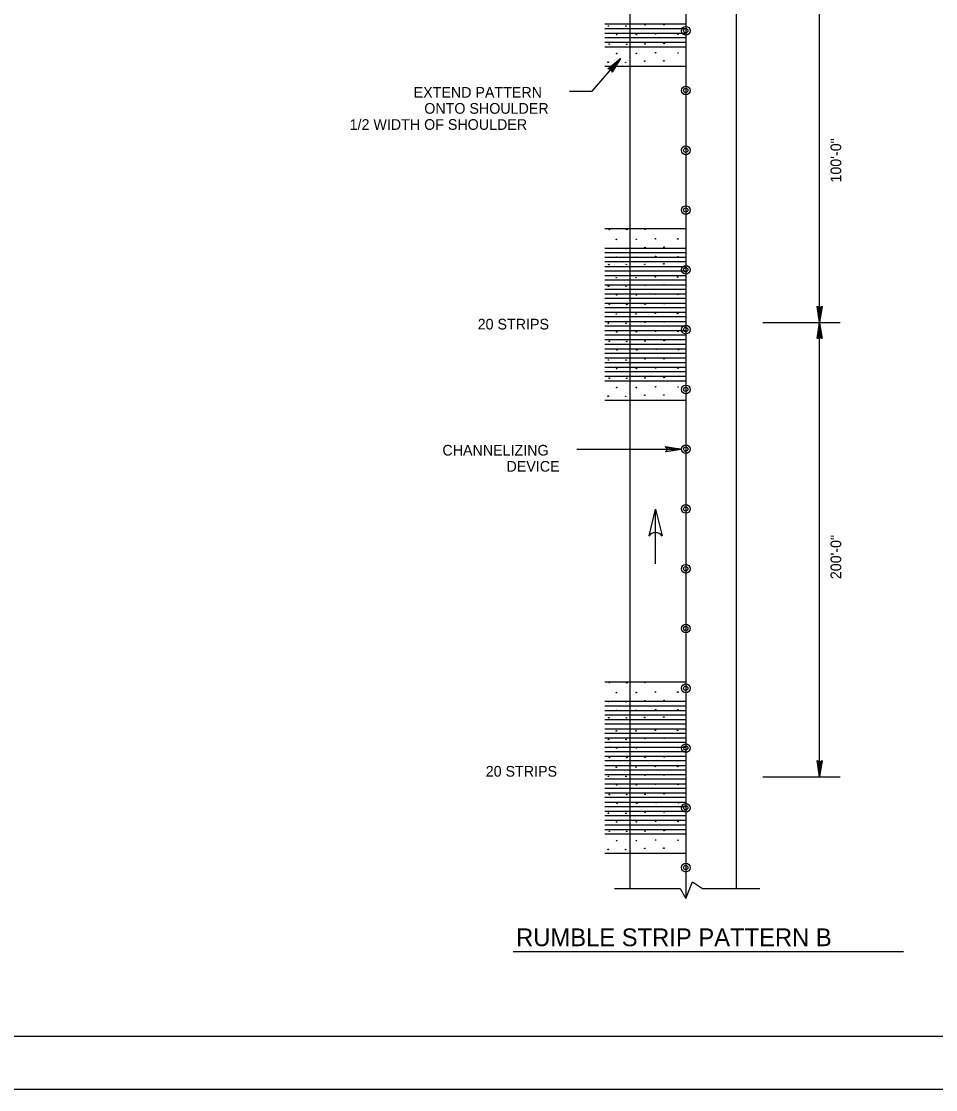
# Model space of a CAD drawing. Extents: x 632008 to 634206, y 294231 to 297795.
# Drawn here: x 632266.3 to 632523.5, y 294230.6 to 294531.2 of the extents above; entities that cross this region are included whole.
import ezdxf

# ---------------------------------------------------------------- set-up
doc = ezdxf.new("R2010")
doc.units = 0
for name, color, linetype in [('1', 7, 'Continuous'), ('Level 1', 7, 'Continuous'), ('Level 2', 7, 'Continuous'), ('Level 3', 7, 'Continuous'), ('PLT-BNDY', 7, 'Continuous')]:
    doc.layers.add(name, color=color, linetype=linetype)

msp = doc.modelspace()

# ---------------------------------------------------------------- linework, layer by layer
at = {"layer": '1'}
msp.add_line((632404.57, 294269.52), (632514.41, 294269.52), dxfattribs=at)
msp.add_lwpolyline([(632833.86, 294245.62), (632833.86, 294809.62), (632047.86, 294809.62), (632047.86, 294245.62), (632833.86, 294245.62), (632833.86, 294271.98), (632633.86, 294271.98), (632633.86, 294336.66), (632833.86, 294336.66), (632833.86, 294365.62), (632633.86, 294365.62), (632633.86, 294245.62), (632712.66, 294245.62), (632712.66, 294271.98), (632712.66, 294245.62), (632789.66, 294245.62), (632789.66, 294271.98), (632789.66, 294259.66), (632833.86, 294259.66)], dxfattribs=at)
at = {"layer": 'Level 1'}
msp.add_line((632422.57, 294410.77), (632451.94, 294410.77), dxfattribs=at)
at = {"layer": 'Level 2'}
for p, q in [((632437.46, 294798.64), (632437.46, 294287.23)), ((632453.13, 294798.64), (632453.17, 294284.41)), ((632467.47, 294287.23), (632467.47, 294798.64)), ((632490.81, 294446.46), (632490.81, 294540.43)), ((632430.37, 294530.44), (632453.13, 294530.44)), ((632430.37, 294529.19), (632453.13, 294529.19)), ((632430.37, 294527.86), (632453.13, 294527.86)), ((632430.37, 294526.62), (632453.13, 294526.62)), ((632430.37, 294525.28), (632453.13, 294525.28)), ((632430.37, 294524.04), (632453.13, 294524.04)), ((632426.81, 294511.49), (632434.77, 294520.76)), ((632430.37, 294518.58), (632453.13, 294518.58)), ((632420.49, 294511.49), (632426.81, 294511.49)), ((632430.37, 294472.85), (632453.13, 294472.85)), ((632430.37, 294467.39), (632453.13, 294467.39)), ((632430.37, 294466.15), (632453.13, 294466.15)), ((632430.37, 294464.81), (632453.13, 294464.81)), ((632430.37, 294463.57), (632453.13, 294463.57)), ((632430.37, 294462.23), (632453.13, 294462.23)), ((632430.37, 294460.99), (632453.13, 294460.99)), ((632430.37, 294459.66), (632453.13, 294459.66)), ((632430.37, 294458.42), (632453.13, 294458.42)), ((632430.37, 294457.08), (632453.13, 294457.08)), ((632430.37, 294455.84), (632453.13, 294455.84)), ((632430.37, 294454.5), (632453.13, 294454.5)), ((632430.37, 294453.26), (632453.13, 294453.26)), ((632430.37, 294451.93), (632453.13, 294451.93)), ((632430.37, 294450.69), (632453.13, 294450.69)), ((632430.37, 294449.35), (632453.13, 294449.35)), ((632430.37, 294448.11), (632453.13, 294448.11)), ((632430.37, 294446.77), (632453.13, 294446.77)), ((632430.37, 294445.53), (632453.13, 294445.53)), ((632430.37, 294444.2), (632453.13, 294444.2)), ((632474.86, 294446.46), (632496.63, 294446.46)), ((632490.81, 294318.66), (632490.81, 294446.46)), ((632430.37, 294442.95), (632453.13, 294442.95)), ((632430.37, 294441.62), (632453.13, 294441.62)), ((632430.37, 294440.38), (632453.13, 294440.38)), ((632430.37, 294439.04), (632453.13, 294439.04)), ((632430.37, 294437.8), (632453.13, 294437.8)), ((632430.37, 294436.47), (632453.13, 294436.47)), ((632430.37, 294435.22), (632453.13, 294435.22)), ((632430.37, 294433.89), (632453.13, 294433.89)), ((632430.37, 294432.65), (632453.13, 294432.65)), ((632430.37, 294431.31), (632453.13, 294431.31)), ((632430.37, 294430.07), (632453.13, 294430.07)), ((632430.37, 294424.61), (632453.13, 294424.61)), ((632442.89, 294386.4), (632444.65, 294393.96)), ((632444.65, 294393.96), (632446.57, 294386.4)), ((632444.65, 294378.51), (632444.65, 294393.96)), ((632430.37, 294345.35), (632453.13, 294345.35)), ((632430.37, 294339.89), (632453.13, 294339.89)), ((632430.37, 294338.64), (632453.13, 294338.64)), ((632430.37, 294337.31), (632453.13, 294337.31)), ((632430.37, 294336.07), (632453.13, 294336.07)), ((632430.37, 294334.73), (632453.13, 294334.73)), ((632430.37, 294333.49), (632453.13, 294333.49)), ((632430.37, 294332.15), (632453.13, 294332.15)), ((632430.37, 294330.91), (632453.13, 294330.91)), ((632430.37, 294329.58), (632453.13, 294329.58)), ((632430.37, 294328.34), (632453.13, 294328.34)), ((632430.37, 294327), (632453.13, 294327)), ((632430.37, 294325.76), (632453.13, 294325.76)), ((632430.37, 294324.42), (632453.13, 294324.42)), ((632430.37, 294323.18), (632453.13, 294323.18)), ((632430.37, 294321.85), (632453.13, 294321.85)), ((632430.37, 294320.61), (632453.13, 294320.61)), ((632430.37, 294319.27), (632453.13, 294319.27)), ((632430.37, 294318.03), (632453.13, 294318.03)), ((632474.84, 294318.66), (632496.61, 294318.66)), ((632430.37, 294316.69), (632453.13, 294316.69)), ((632430.37, 294315.45), (632453.13, 294315.45)), ((632430.37, 294314.12), (632453.13, 294314.12)), ((632430.37, 294312.88), (632453.13, 294312.88)), ((632430.37, 294311.54), (632453.13, 294311.54)), ((632430.37, 294310.3), (632453.13, 294310.3)), ((632430.37, 294308.96), (632453.13, 294308.96)), ((632430.37, 294307.72), (632453.13, 294307.72)), ((632430.37, 294306.39), (632453.13, 294306.39)), ((632430.37, 294305.15), (632453.13, 294305.15)), ((632430.37, 294303.81), (632453.13, 294303.81)), ((632430.37, 294302.57), (632453.13, 294302.57)), ((632430.37, 294297.11), (632453.13, 294297.11))]:
    msp.add_line(p, q, dxfattribs=at)
for centre, radius in [((632431.42, 294529.87), 0.0832), ((632436.34, 294529.84), 0.0832), ((632441.72, 294530.14), 0.0832), ((632447.07, 294530.21), 0.0832), ((632453.17, 294528.53), 1.23), ((632453.17, 294528.54), 0.601), ((632433.71, 294527.42), 0.0832), ((632439.27, 294527.44), 0.0832), ((632444.69, 294527.62), 0.0832), ((632450.98, 294527.55), 0.0832), ((632431.64, 294524.77), 0.0832), ((632436.56, 294524.74), 0.0832), ((632441.72, 294524.84), 0.0832), ((632444.69, 294522.33), 0.0832), ((632447.1, 294524.96), 0.0832), ((632450.98, 294522.26), 0.0832), ((632431.34, 294519.68), 0.0832), ((632433.71, 294522.13), 0.0832), ((632436.27, 294519.65), 0.0832), ((632439.28, 294522.14), 0.0832), ((632441.64, 294519.96), 0.0832), ((632447, 294520.03), 0.0832), ((632453.17, 294511.71), 1.23), ((632453.17, 294511.73), 0.601), ((632453.17, 294494.89), 1.23), ((632453.17, 294494.91), 0.601), ((632453.17, 294478.08), 1.23), ((632453.17, 294478.09), 0.601), ((632431.65, 294472.61), 0.0832), ((632431.65, 294472.61), 0.0832), ((632436.58, 294472.58), 0.0832), ((632436.58, 294472.58), 0.0832), ((632441.74, 294472.68), 0.0832), ((632441.74, 294472.68), 0.0832), ((632433.67, 294469.82), 0.0832), ((632439.23, 294469.84), 0.0832), ((632444.64, 294470.02), 0.0832), ((632450.94, 294469.95), 0.0832), ((632431.4, 294467.29), 0.0832), ((632436.33, 294467.26), 0.0832), ((632441.71, 294467.56), 0.0832), ((632447.06, 294467.63), 0.0832), ((632431.53, 294462.74), 0.0832), ((632433.7, 294464.84), 0.0832), ((632436.46, 294462.71), 0.0832), ((632439.26, 294464.86), 0.0832), ((632441.62, 294462.81), 0.0832), ((632444.67, 294465.05), 0.0832), ((632446.99, 294462.94), 0.0832), ((632450.97, 294464.97), 0.0832), ((632453.17, 294461.26), 1.23), ((632444.6, 294459.26), 0.0832), ((632450.89, 294459.19), 0.0832), ((632453.17, 294461.27), 0.601), ((632431.43, 294456.66), 0.0832), ((632433.62, 294459.06), 0.0832), ((632436.36, 294456.63), 0.0832), ((632439.18, 294459.07), 0.0832), ((632441.74, 294456.94), 0.0832), ((632447.09, 294457.01), 0.0832), ((632433.73, 294454.22), 0.0832), ((632439.29, 294454.23), 0.0832), ((632444.7, 294454.42), 0.0832), ((632451, 294454.35), 0.0832), ((632431.65, 294451.56), 0.0832), ((632436.58, 294451.53), 0.0832), ((632441.74, 294451.63), 0.0832), ((632447.11, 294451.76), 0.0832), ((632433.62, 294448.84), 0.0832), ((632439.18, 294448.86), 0.0832), ((632444.6, 294449.05), 0.0832), ((632450.89, 294448.98), 0.0832), ((632431.42, 294446.27), 0.0832), ((632436.34, 294446.24), 0.0832), ((632441.72, 294446.54), 0.0832), ((632447.07, 294446.61), 0.0832), ((632453.17, 294444.44), 1.23), ((632453.17, 294444.45), 0.601), ((632431.64, 294441.16), 0.0832), ((632433.71, 294443.82), 0.0832), ((632436.56, 294441.13), 0.0832), ((632439.27, 294443.84), 0.0832), ((632441.72, 294441.23), 0.0832), ((632444.69, 294444.02), 0.0832), ((632447.1, 294441.36), 0.0832), ((632450.98, 294443.95), 0.0832), ((632433.85, 294438.71), 0.0832), ((632439.41, 294438.72), 0.0832), ((632444.83, 294438.91), 0.0832), ((632451.12, 294438.84), 0.0832), ((632431.42, 294435.9), 0.0832), ((632436.34, 294435.87), 0.0832), ((632441.72, 294436.17), 0.0832), ((632447.07, 294436.24), 0.0832), ((632433.71, 294433.45), 0.0832), ((632439.27, 294433.47), 0.0832), ((632444.69, 294433.65), 0.0832), ((632450.98, 294433.58), 0.0832), ((632431.64, 294430.79), 0.0832), ((632436.56, 294430.77), 0.0832), ((632441.72, 294430.87), 0.0832), ((632447.1, 294430.99), 0.0832), ((632433.71, 294428.16), 0.0832), ((632439.28, 294428.17), 0.0832), ((632444.69, 294428.36), 0.0832), ((632450.98, 294428.29), 0.0832), ((632453.17, 294427.62), 1.23), ((632453.17, 294427.64), 0.601), ((632431.34, 294425.71), 0.0832), ((632436.27, 294425.68), 0.0832), ((632441.64, 294425.99), 0.0832), ((632447, 294426.06), 0.0832), ((632453.17, 294410.8), 1.23), ((632453.17, 294410.82), 0.601), ((632453.17, 294393.99), 1.23), ((632453.17, 294394), 0.601), ((632453.17, 294377.17), 1.23), ((632453.17, 294377.18), 0.601), ((632453.17, 294360.35), 1.23), ((632453.17, 294360.36), 0.601), ((632431.65, 294345.11), 0.0832), ((632431.65, 294345.11), 0.0832), ((632436.58, 294345.08), 0.0832), ((632436.58, 294345.08), 0.0832), ((632441.74, 294345.18), 0.0832), ((632441.74, 294345.18), 0.0832), ((632433.67, 294342.32), 0.0832), ((632439.23, 294342.34), 0.0832), ((632444.64, 294342.52), 0.0832), ((632450.94, 294342.45), 0.0832), ((632453.17, 294343.53), 1.23), ((632453.17, 294343.55), 0.601), ((632431.4, 294339.79), 0.0832), ((632436.33, 294339.76), 0.0832), ((632441.71, 294340.06), 0.0832), ((632447.06, 294340.13), 0.0832), ((632433.7, 294337.34), 0.0832), ((632439.26, 294337.36), 0.0832), ((632444.67, 294337.54), 0.0832), ((632450.97, 294337.47), 0.0832), ((632431.53, 294335.24), 0.0832), ((632436.46, 294335.21), 0.0832), ((632441.62, 294335.31), 0.0832), ((632446.99, 294335.44), 0.0832), ((632433.62, 294331.56), 0.0832), ((632439.18, 294331.57), 0.0832), ((632444.6, 294331.76), 0.0832), ((632450.89, 294331.69), 0.0832), ((632431.43, 294329.16), 0.0832), ((632436.36, 294329.13), 0.0832), ((632441.74, 294329.44), 0.0832), ((632444.7, 294326.92), 0.0832), ((632447.09, 294329.51), 0.0832), ((632453.17, 294326.71), 1.23), ((632453.17, 294326.73), 0.601), ((632431.65, 294324.06), 0.0832), ((632433.73, 294326.72), 0.0832), ((632436.58, 294324.03), 0.0832), ((632439.29, 294326.73), 0.0832), ((632441.74, 294324.13), 0.0832), ((632447.11, 294324.25), 0.0832), ((632451, 294326.85), 0.0832), ((632433.62, 294321.34), 0.0832), ((632439.18, 294321.36), 0.0832), ((632444.6, 294321.55), 0.0832), ((632450.89, 294321.48), 0.0832), ((632431.42, 294318.77), 0.0832), ((632436.34, 294318.74), 0.0832), ((632441.72, 294319.04), 0.0832), ((632447.07, 294319.11), 0.0832), ((632433.71, 294316.32), 0.0832), ((632439.27, 294316.33), 0.0832), ((632444.69, 294316.52), 0.0832), ((632450.98, 294316.45), 0.0832), ((632431.64, 294313.66), 0.0832), ((632436.56, 294313.63), 0.0832), ((632441.72, 294313.73), 0.0832), ((632447.1, 294313.86), 0.0832), ((632433.85, 294311.2), 0.0832), ((632439.41, 294311.22), 0.0832), ((632444.83, 294311.41), 0.0832), ((632451.12, 294311.34), 0.0832), ((632453.17, 294309.9), 1.23), ((632453.17, 294309.91), 0.601), ((632431.42, 294308.4), 0.0832), ((632433.71, 294305.95), 0.0832), ((632436.34, 294308.37), 0.0832), ((632439.27, 294305.97), 0.0832), ((632441.72, 294308.67), 0.0832), ((632444.69, 294306.15), 0.0832), ((632447.07, 294308.74), 0.0832), ((632450.98, 294306.08), 0.0832), ((632431.64, 294303.29), 0.0832), ((632436.56, 294303.26), 0.0832), ((632441.72, 294303.36), 0.0832), ((632447.1, 294303.49), 0.0832), ((632433.71, 294300.66), 0.0832), ((632439.28, 294300.67), 0.0832), ((632444.69, 294300.86), 0.0832), ((632450.98, 294300.79), 0.0832), ((632431.34, 294298.21), 0.0832), ((632436.27, 294298.18), 0.0832), ((632441.64, 294298.49), 0.0832), ((632447, 294298.56), 0.0832), ((632453.17, 294293.08), 1.23), ((632453.17, 294293.09), 0.601)]:
    msp.add_circle(centre, radius, dxfattribs=at)
msp.add_arc((632444.65, 294384.97), 2.34, 36.8699, 143.1301, dxfattribs=at)
at = {"layer": 'Level 3'}
for p, q in [((632453.17, 294284.41), (632455.09, 294289.13)), ((632455.09, 294289.13), (632457.9, 294287.21)), ((632433.16, 294287.21), (632451.58, 294287.21)), ((632451.58, 294287.21), (632453.17, 294284.41)), ((632457.9, 294287.21), (632474.05, 294287.21))]:
    msp.add_line(p, q, dxfattribs=at)
for points in [[(632431.61, 294517.85), (632431.98, 294517.74), (632434.77, 294520.76), (632431.61, 294517.85), (632431.26, 294517.81), (632434.77, 294520.76), (632432.19, 294517.41), (632432.42, 294517.09), (632434.77, 294520.76), (632432.45, 294516.9), (632432.42, 294517.09)], [(632491.35, 294450.86), (632491, 294450.68), (632490.81, 294446.46), (632491.35, 294450.86), (632491.51, 294451.03), (632490.81, 294446.46), (632490.64, 294450.68), (632490.29, 294450.86), (632490.81, 294446.46), (632490.11, 294451.03), (632490.29, 294450.86)], [(632490.29, 294442.08), (632490.64, 294442.25), (632490.81, 294446.46), (632490.29, 294442.08), (632490.11, 294441.9), (632490.81, 294446.46), (632491, 294442.25), (632491.35, 294442.08), (632490.81, 294446.46), (632491.51, 294441.9), (632491.35, 294442.08)], [(632447.69, 294411.32), (632447.84, 294410.96), (632451.94, 294410.77), (632447.69, 294411.32), (632447.43, 294411.55), (632451.94, 294410.77), (632447.72, 294410.59), (632447.62, 294410.2), (632451.94, 294410.77), (632447.5, 294410.06), (632447.62, 294410.2)], [(632491.35, 294323.03), (632491, 294322.84), (632490.81, 294318.63), (632491.35, 294323.03), (632491.51, 294323.19), (632490.81, 294318.63), (632490.64, 294322.84), (632490.29, 294323.03), (632490.81, 294318.63), (632490.11, 294323.19), (632490.29, 294323.03)]]:
    msp.add_lwpolyline(points, dxfattribs=at)
at = {"layer": 'PLT-BNDY'}
msp.add_lwpolyline([(632007.86, 294824.62), (632848.86, 294824.62), (632848.86, 294230.62), (632007.86, 294230.62)], close=True, dxfattribs=at)

# ---------------------------------------------------------------- texts
at = {"layer": 'Level 2'}
for s, height, p in [('EXTEND PATTERN', 3, (632376.61, 294509.7)), ('ONTO SHOULDER', 3, (632379.61, 294505.18)), ('1/2 WIDTH OF SHOULDER', 3, (632358.61, 294500.65)), ('20 STRIPS', 3, (632394.63, 294444.48)), ('CHANNELIZING', 3, (632384.71, 294409.01)), ('DEVICE', 3, (632402.74, 294404.48)), ('20 STRIPS', 3, (632396.9, 294318.68)), ('RUMBLE STRIP PATTERN B', 5, (632405.44, 294270.98))]:
    msp.add_text(s, height=height, dxfattribs=at).set_placement(p)
for s, p in [('100\'-0"', (632496.9, 294485.81)), ('200\'-0"', (632496.9, 294374.23))]:
    msp.add_text(s, height=3, rotation=90, dxfattribs=at).set_placement(p)

doc.saveas('drawing.dxf')
